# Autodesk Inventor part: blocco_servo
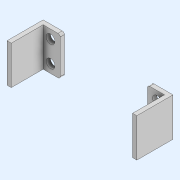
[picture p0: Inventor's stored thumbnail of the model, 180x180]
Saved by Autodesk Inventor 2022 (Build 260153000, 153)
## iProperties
Created: 2021-12
Part Number: blocco_servo
Material: Generico
Document SubType Name: Modeling
Designer: admin
Density: 1 g/cm^3
Appearance: Default
Author: admin
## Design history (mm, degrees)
extrude "Estrusione1" new body sketch "Schizzo1" distance "d1" = 2; taper "d2" = 0 deg
sketch "Schizzo2"
  geometry: L1 (-5.5, 4.05)-(-5.5, -14.05) reference; L2 (-5.5, -14.05)-(4.5, -14.05) reference; L3 (-5.5, 4.05)-(-3.5, 4.05); L4 (-3.5, 4.05)-(-3.5, -14.05); L5 (-3.5, -14.05)-(-5.5, -14.05); L6 (-5.5, -14.05)-(-5.5, 4.05); 1 further point
  constraints: 8 end point, 2 parallel, 1 horizontal, 1 perpendicular, 1 point on line
  dimensions: "d4" = 2 distance of L4.end L5.end
extrude "Estrusione2" join sketch "Schizzo2" distance "d5" = 15; taper "d6" = 0 deg
node "Piano di lavoro1"
mirror "Specchio1"
fillet "Raccordo1" dims "d7" = 1
node "Solido1"
node "Piano di lavoro2"
other parameters: "d0" = 8, "d3" = 2
